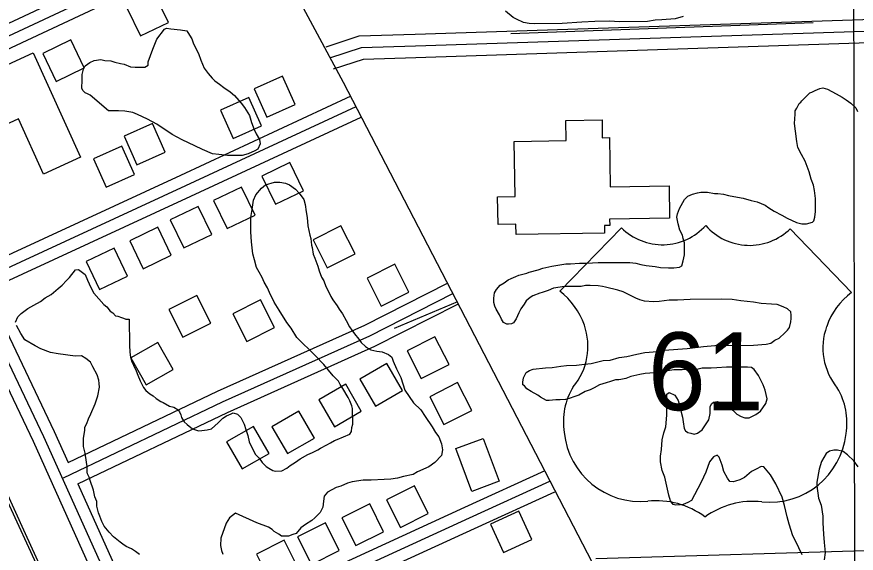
# Model space of a CAD drawing. Extents: x 3313442 to 3351311, y 721974 to 747360.
# Drawn here: x 3326984 to 3328063, y 738094 to 738784 of the extents above; entities that cross this region are included whole.
import ezdxf

# ---------------------------------------------------------------- set-up
doc = ezdxf.new("R2010")
doc.units = 0
for name, color, linetype in [('V-BLDG-OTLN', 7, 'Continuous'), ('V-GRID-MAJR', 7, 'Continuous'), ('V-RAIL-TRAK', 7, 'Continuous'), ('V-ROAD-CNTR', 7, 'Continuous'), ('V-ROAD-IDEN', 7, 'Continuous'), ('V-SITE-VEGE', 7, 'Continuous'), ('V-TOPO-SHOR', 7, 'Continuous')]:
    doc.layers.add(name, color=color, linetype=linetype)

msp = doc.modelspace()

# ---------------------------------------------------------------- linework, layer by layer
at = {"layer": 'V-BLDG-OTLN'}
for points in [[(3327162, 738812.9), (3327126, 738795.4), (3327143.5, 738759.4), (3327179.5, 738776.9)], [(3327053.7, 738754.3), (3327017.7, 738736.8), (3327035.2, 738700.8), (3327071.2, 738718.3)], [(3327005.4, 738737.5), (3327066.4, 738603.5), (3327018.9, 738581.9), (3326986.5, 738652.9), (3326962.2, 738641.8), (3326933.5, 738704.8)], [(3327305.6, 738654.9), (3327342.1, 738671.2), (3327325.8, 738707.7), (3327289.3, 738691.4)], [(3327262.6, 738627.4), (3327299.1, 738643.7), (3327282.8, 738680.2), (3327246.3, 738663.9)], [(3327602.9, 738517), (3327602.4, 738552.5), (3327624.7, 738552.8), (3327623.5, 738623.8), (3327690.3, 738624.9), (3327689.9, 738650.7), (3327736.5, 738651.5), (3327736.8, 738628.6), (3327746, 738628.7), (3327747, 738565.4), (3327822.6, 738566.6), (3327823.2, 738525.1), (3327746.3, 738523.9), (3327746.4, 738515.7), (3327739.8, 738515.6), (3327739.9, 738506), (3327626.1, 738504.2), (3327625.9, 738517.4)], [(3327138.7, 738593.9), (3327175.2, 738610.2), (3327158.9, 738646.7), (3327122.4, 738630.5)], [(3327099.3, 738565), (3327135.9, 738581.3), (3327119.6, 738617.9), (3327083, 738601.6)], [(3327335.4, 738596.5), (3327299.4, 738579.2), (3327316.7, 738543.1), (3327352.7, 738560.5)], [(3327273.4, 738565), (3327237.4, 738547.7), (3327254.7, 738511.7), (3327290.8, 738529)], [(3327217.6, 738540.2), (3327181.6, 738522.8), (3327199, 738486.8), (3327235, 738504.1)], [(3327165.6, 738513.4), (3327129.5, 738496), (3327146.9, 738460), (3327182.9, 738477.4)], [(3327419.1, 738479.5), (3327400.9, 738515.2), (3327365.3, 738497.1), (3327383.4, 738461.4)], [(3327109.4, 738486.7), (3327073.4, 738469.3), (3327090.7, 738433.3), (3327126.8, 738450.6)], [(3327488.4, 738430.2), (3327470.3, 738465.9), (3327434.6, 738447.8), (3327452.7, 738412.1)], [(3327233.7, 738390.3), (3327215.6, 738425.9), (3327179.9, 738407.8), (3327198, 738372.1)], [(3327315.6, 738384.5), (3327297.5, 738420.2), (3327261.9, 738402.1), (3327280, 738366.4)], [(3327539.9, 738337.2), (3327521.8, 738372.8), (3327486.1, 738354.7), (3327504.2, 738319.1)], [(3327150.7, 738310.7), (3327185.4, 738330.6), (3327165.5, 738365.3), (3327130.8, 738345.4)], [(3327445.2, 738283.5), (3327479.9, 738303.4), (3327460, 738338.1), (3327425.3, 738318.2)], [(3327392.5, 738257), (3327427.1, 738276.9), (3327407.2, 738311.6), (3327372.5, 738291.7)], [(3327569, 738278.1), (3327550.9, 738313.8), (3327515.2, 738295.6), (3327533.4, 738260)], [(3327332.1, 738222.4), (3327366.8, 738242.3), (3327346.9, 738277), (3327312.2, 738257.1)], [(3327273.9, 738202.9), (3327308.6, 738222.8), (3327288.7, 738257.5), (3327254, 738237.6)], [(3327569.3, 738173.8), (3327548.7, 738228.9), (3327583.8, 738242), (3327604.4, 738186.9)], [(3327477.6, 738127.4), (3327513.3, 738145.3), (3327495.5, 738181.1), (3327459.7, 738163.2)], [(3327420, 738104.2), (3327455.8, 738122.1), (3327438, 738157.9), (3327402.2, 738140)], [(3327646.3, 738112.1), (3327629.6, 738148.4), (3327593.2, 738131.8), (3327609.9, 738095.4)], [(3327363, 738079.8), (3327398.8, 738097.7), (3327381, 738133.4), (3327345.2, 738115.6)], [(3327310.3, 738057.3), (3327346.1, 738075.2), (3327328.2, 738111), (3327292.4, 738093.1)]]:
    msp.add_lwpolyline(points, close=True, dxfattribs=at)
at = {"layer": 'V-GRID-MAJR'}
msp.add_spline([(3328075.1, 727366.3), (3328067.1, 733424.9), (3328059.2, 739486.7), (3328051.3, 745548.5), (3328051.3, 745551.5)], degree=3, dxfattribs=at)
at = {"layer": 'V-RAIL-TRAK'}
msp.add_lwpolyline([(3327407.2, 737206.7), (3327346, 737342.7), (3327255.2, 737542), (3327151.4, 737770.4), (3327055.5, 737980.5), (3327019.5, 738058.9), (3326965.1, 738177.2), (3326868.8, 738389.1), (3326793.1, 738556.9), (3326699.8, 738760.5), (3326584.4, 739013.9)], dxfattribs=at)
at = {"layer": 'V-ROAD-CNTR'}
msp.add_line((3327469.7, 738383.7), (3327551, 738418), dxfattribs=at)
for points in [[(3327059, 739341.5), (3327403.8, 738699.8)], [(3326851.1, 738718.6), (3327285.4, 738921.9)], [(3326857.4, 738705), (3327291.8, 738908.3)], [(3326863.8, 738691.4), (3327298.1, 738894.8)], [(3327386.9, 738731.4), (3327427.2, 738744.4), (3327496.6, 738746.7), (3329869.9, 738824.8)], [(3327382.2, 738745.6), (3327424.6, 738759.4), (3327496.2, 738761.7), (3328176.2, 738784.1)], [(3327391.5, 738717.1), (3327429.8, 738729.5), (3327497.1, 738731.7), (3328390.2, 738761.1)], [(3327403.8, 738699.8), (3328760.8, 736081.2)], [(3327413.8, 738681.9), (3327195, 738580.2), (3326933.1, 738459.2)], [(3327420.1, 738668.3), (3327201.3, 738566.6), (3326926, 738439.3), (3326926.7, 738437.4)], [(3327426.5, 738654.7), (3327207.6, 738552.9), (3326946, 738432.1)], [(3328479, 734877.1), (3327825, 736304.4), (3326995.4, 738119.3), (3326777.2, 738600.5)], [(3326912.1, 738468.3), (3327018.9, 738244.6), (3327212.6, 737813.3), (3327328.5, 737562.7), (3327539.8, 737106.8), (3327748.9, 736642.6), (3327981.7, 736133.7), (3328101.7, 735880.4), (3328340.2, 735352.9), (3328536.1, 734929.8)], [(3326898.6, 738461.8), (3327005.3, 738238.3), (3327198.9, 737807.1), (3327314.9, 737556.4), (3327526.2, 737100.6), (3327735.2, 736636.4), (3327968.1, 736127.4), (3328035.4, 735985.4)], [(3327050.5, 738211), (3327242.4, 738302.6), (3327431.7, 738387.4), (3327537.8, 738441.5)], [(3326946, 738432.1), (3327032.5, 738250.9), (3327050.5, 738211)], [(3327044.3, 738191.5), (3327248.7, 738288.9), (3327438.2, 738373.9), (3327544.6, 738428.1)], [(3327062.8, 738183.6), (3327255, 738275.3), (3327444.7, 738360.4), (3327551.4, 738414.7)], [(3327156.9, 737974), (3327357.3, 738060.4), (3327560.2, 738153.4), (3327663.3, 738200.6)], [(3327149.2, 737954.4), (3327363.4, 738046.7), (3327566.4, 738139.8), (3327669.6, 738187)], [(3327062.8, 738183.6), (3327156.9, 737974)], [(3327169.2, 737946.7), (3327369.4, 738033), (3327572.7, 738126.2), (3327675.8, 738173.3)], [(3328103.5, 738098.3), (3327728.7, 738087)]]:
    msp.add_lwpolyline(points, dxfattribs=at)
at = {"layer": 'V-ROAD-IDEN'}
for p, q in [((3327682.2, 738431.1), (3327761.4, 738512.8)), ((3327682.2, 738431.1), (3327761.4, 738512.8)), ((3327978.5, 738511.6), (3328057.2, 738429.4)), ((3328057.2, 738429.4), (3327978.5, 738511.6)), ((3327682.2, 738431.1), (3327682.2, 738431.1))]:
    msp.add_line(p, q, dxfattribs=at)
for centre, major_axis, start_param, end_param in [((3327814.2, 738566), (-0.1, -75), 5.502702, 7.121811), ((3327814.2, 738566), (-0.1, -75), 5.502702, 7.121811), ((3327926.1, 738565.2), (0.1, 75), 2.291842, 3.917604), ((3327926.1, 738565.2), (0.1, 75), 2.291842, 3.917604), ((3327626.8, 738357.5), (0.1, 92.2), 5.045266, 5.638568), ((3327626.8, 738357.5), (0.1, 92.2), 5.045266, 5.638568), ((3328112, 738355.4), (-0.1, -92.2), 3.781672, 4.374974), ((3328112, 738355.4), (-0.1, -92.2), 3.781672, 4.374974), ((3327636.9, 738360.6), (0.1, 81.7), 4.021008, 5.049788), ((3327636.9, 738360.6), (0.1, 81.7), 4.021008, 5.049788), ((3328101.9, 738358.5), (-0.1, -81.7), 4.370452, 5.399232), ((3328101.9, 738358.5), (-0.1, -81.7), 4.370452, 5.399232), ((3327773.1, 738263.2), (-0.1, -86.5), 4.163028, 4.868958), ((3327773.1, 738263.2), (-0.1, -86.5), 4.163028, 4.868958), ((3327965, 738262.1), (0.1, 86.5), 4.551282, 5.257212), ((3327965, 738262.1), (0.1, 86.5), 4.551282, 5.257212), ((3327786, 738259.7), (0.1, 98.8), 1.672766, 3.238327), ((3327786, 738259.7), (0.1, 98.8), 1.672766, 3.238327), ((3327952.1, 738258.8), (-0.1, -98.8), 6.181885, 7.747479), ((3327952.1, 738258.8), (-0.1, -98.8), 6.181885, 7.747479), ((3327806, 738056.3), (0.1, 105.6), 5.646836, 6.385311), ((3327806, 738056.3), (0.1, 105.6), 5.646836, 6.385311), ((3327930.7, 738055.5), (-0.1, -105.6), 3.034929, 3.773404), ((3327930.7, 738055.5), (-0.1, -105.6), 3.034929, 3.773404)]:
    msp.add_ellipse(centre, major_axis=major_axis, ratio=0.99789, start_param=start_param, end_param=end_param, dxfattribs=at)
at = {"layer": 'V-SITE-VEGE'}
for points in [[(3327840.8, 738784.5), (3327830.4, 738781.3), (3327813.3, 738780), (3327804.8, 738779.9), (3327795, 738778), (3327758.9, 738777.7), (3327746.1, 738778.2), (3327727.1, 738778), (3327710.6, 738777.3), (3327685.5, 738775.3), (3327650.1, 738775), (3327642.7, 738775.5), (3327635.4, 738776.7), (3327626.8, 738780.9), (3327622.5, 738783.3), (3327612.6, 738791.2)], [(3327993.3, 738676.2), (3327999.4, 738681.8), (3328003.7, 738686.1), (3328006.1, 738687.3), (3328010.4, 738689.2), (3328016.5, 738691.7), (3328020.1, 738692.9), (3328026.2, 738691.2), (3328037.3, 738685.1), (3328045.3, 738680.9), (3328050.2, 738677.3), (3328056.4, 738673.1), (3328062.5, 738667), (3328065, 738662.1)], [(3327659.6, 738429.5), (3327656.5, 738428.9), (3327647.4, 738425.1), (3327644.3, 738423.3), (3327638.9, 738419), (3327636.5, 738414.7), (3327632.2, 738408.5), (3327629.8, 738403.6), (3327626.2, 738395.6), (3327622.6, 738390.7), (3327620.1, 738389.5), (3327616.5, 738388.8), (3327614, 738388.8), (3327609.7, 738391.2), (3327607.3, 738395.5), (3327604.8, 738401), (3327600.4, 738408.3), (3327598.6, 738411.9), (3327597.3, 738416.8), (3327597.3, 738422.3), (3327598.4, 738429), (3327600.8, 738433.3), (3327605.7, 738438.9), (3327610.6, 738442), (3327616, 738445.7), (3327619.7, 738447.6), (3327625.8, 738450), (3327629.4, 738451.9), (3327639.8, 738454.4), (3327642.9, 738455.7), (3327654.5, 738458.8), (3327660.5, 738460.7), (3327672.1, 738463.3), (3327689.9, 738466.5), (3327696, 738466.5), (3327707.6, 738467.2), (3327716.8, 738467.3), (3327731.4, 738468), (3327772.4, 738468.3), (3327779.8, 738467.2), (3327786.5, 738465.4), (3327793.2, 738464.2), (3327804.9, 738463.1), (3327811.6, 738461.9), (3327822, 738461.4), (3327828.7, 738461.5), (3327836.1, 738462.1), (3327839.1, 738464), (3327840.9, 738470.1), (3327842.7, 738478.1), (3327842.5, 738493.4), (3327840.7, 738498.9), (3327840, 738503.1), (3327836.3, 738509.8), (3327834.4, 738517.8), (3327832.5, 738526.3), (3327833.7, 738530.6), (3327836.1, 738537.4), (3327842.7, 738549), (3327846.9, 738553.3), (3327853, 738555.8), (3327859.1, 738557.7), (3327863.4, 738558.4), (3327872, 738558.4), (3327881.2, 738556.7), (3327885.4, 738556.7), (3327892.8, 738556.2), (3327898.9, 738554.4), (3327910.6, 738552), (3327917.9, 738550.9), (3327928.3, 738547.9), (3327935.7, 738546.1), (3327946.1, 738541.9), (3327951, 738538.3), (3327957.8, 738534), (3327967.6, 738529.2), (3327974.4, 738525), (3327986.6, 738519.6), (3327993.4, 738517.8), (3327999.5, 738517.9), (3328006.8, 738519.8), (3328008.6, 738521.6), (3328009.8, 738526.5), (3328011, 738533.9), (3328010.9, 738550.4), (3328009.6, 738560.8), (3328008.3, 738567.5), (3328005.2, 738575.4), (3328002.6, 738584.6), (3327997.6, 738598.6), (3327992.7, 738607.1), (3327988.3, 738616.2), (3327987, 738623.6), (3327985.1, 738637), (3327983.8, 738646.8), (3327984.9, 738659), (3327984.9, 738663.3), (3327986.7, 738666.4), (3327989.7, 738672.5), (3327992.1, 738674.4), (3327993.3, 738676.2)], [(3327121.6, 738396.7), (3327124.6, 738395.5), (3327128.9, 738395.5), (3327129.2, 738361.9), (3327129.9, 738352.7), (3327130.5, 738346.6), (3327132.4, 738340.5), (3327134.3, 738336.3), (3327138, 738329), (3327139.9, 738323.5), (3327143, 738316.2), (3327147.3, 738307.6), (3327150.4, 738303.4), (3327155.4, 738299.1), (3327159.7, 738296.7), (3327163.4, 738293.1), (3327169.5, 738289.5), (3327172.6, 738288.3), (3327180.6, 738283.4), (3327186.1, 738282.2), (3327191.6, 738278.6), (3327193.5, 738276.2), (3327195.3, 738272.5), (3327196, 738268.9), (3327199.7, 738263.4), (3327203.4, 738259.8), (3327210.2, 738254.3), (3327218.1, 738251.9), (3327222.4, 738252), (3327229.1, 738253.2), (3327234.6, 738254.5), (3327243.1, 738261.9), (3327249.2, 738268.1), (3327254, 738271.2), (3327260.1, 738273.7), (3327262.6, 738274.9), (3327268.1, 738273.1), (3327272.4, 738268.9), (3327276.8, 738260.3), (3327278.6, 738253.6), (3327281.2, 738245.7), (3327283.1, 738237.8), (3327287.4, 738228.6), (3327291.1, 738221.3), (3327296.1, 738216.5), (3327299.8, 738211), (3327304.7, 738206.1), (3327308.4, 738203.7), (3327313.3, 738200.7), (3327316.4, 738200.1), (3327324.9, 738200.2), (3327331.6, 738203.9), (3327335.9, 738207), (3327342.6, 738211.3), (3327348.7, 738215.7), (3327358.4, 738221.3), (3327364.5, 738223.7), (3327371.2, 738227.5), (3327374.9, 738229.3), (3327382.8, 738233.7), (3327387.6, 738236.2), (3327392.5, 738239.3), (3327396.2, 738240.5), (3327412.6, 738247.4), (3327414.4, 738251.1), (3327415, 738256), (3327416.2, 738260.2), (3327416, 738280.4), (3327414.8, 738284.1), (3327412.3, 738290.2), (3327410.4, 738294.4), (3327403.6, 738306), (3327399.9, 738311.5), (3327398, 738315.8), (3327391.2, 738322.4), (3327378.9, 738337), (3327367.8, 738348.5), (3327344.4, 738371.6), (3327336.9, 738383.8), (3327331.4, 738391), (3327321.5, 738406.9), (3327315.2, 738417.2), (3327309, 738429.4), (3327306.5, 738435.5), (3327302.2, 738442.8), (3327299.7, 738448.9), (3327296, 738455.6), (3327292.3, 738461.7), (3327289.7, 738471.4), (3327287.8, 738479.4), (3327285.9, 738494.6), (3327285.2, 738507.5), (3327285, 738525.8), (3327286.8, 738536.2), (3327288.5, 738548.5), (3327291.5, 738555.2), (3327298.8, 738563.9), (3327304.2, 738568.2), (3327315.8, 738571.3), (3327322.6, 738571.4), (3327329.9, 738570.2)], [(3327329.9, 738570.2), (3327334.8, 738567.8), (3327342.8, 738562.4), (3327347.1, 738557.5), (3327353.3, 738549), (3327355.2, 738542.9), (3327356.5, 738533.1), (3327357.8, 738525.8), (3327358.5, 738515.4), (3327361, 738503.2), (3327362.3, 738498.9), (3327363, 738490.4), (3327364.2, 738487.3), (3327365.5, 738478.8), (3327367.4, 738473.9), (3327371.1, 738463.5), (3327373, 738457.4), (3327376.1, 738449.5), (3327379.2, 738444.6), (3327381.7, 738437.3), (3327384.2, 738432.4), (3327388, 738424.5), (3327390.4, 738420.3), (3327396, 738412.4), (3327398.5, 738408.1), (3327402.8, 738402), (3327407.8, 738393.5), (3327412.1, 738385.6), (3327415.2, 738381.3), (3327418.3, 738376.5), (3327423.9, 738369.8), (3327427, 738365.5), (3327432.5, 738360.1), (3327436.2, 738357.6), (3327439.3, 738355.8), (3327447.2, 738354.1), (3327454, 738353.5), (3327462, 738349.9), (3327466.3, 738346.3), (3327468.1, 738341.4), (3327472.5, 738331.6), (3327478.1, 738320.1), (3327483.1, 738304.2), (3327494.3, 738287.8), (3327503.5, 738278.7), (3327509.1, 738270.2), (3327518.4, 738256.8), (3327522.7, 738249.5), (3327527, 738244), (3327530.1, 738234.9), (3327531.4, 738227.5), (3327530.3, 738220.2), (3327521.8, 738210.9), (3327513.9, 738205.4), (3327499.2, 738199.1), (3327493.8, 738195.4), (3327481.6, 738192.9), (3327473.6, 738191), (3327465.1, 738189.7), (3327456.5, 738189), (3327440, 738188.3), (3327429.6, 738188.2), (3327415.6, 738186.2), (3327409.5, 738184.4), (3327400.9, 738180.6), (3327394.8, 738178.7), (3327383.9, 738173.1), (3327379.6, 738167.6), (3327378.5, 738161.5), (3327377.9, 738153.5), (3327374.3, 738146.8), (3327367.6, 738140), (3327363.4, 738136.3), (3327355.5, 738131.3), (3327349.4, 738127), (3327343.3, 738119.6), (3327339.1, 738118.4), (3327333.6, 738116.5), (3327324.4, 738116.4), (3327321.3, 738118.8), (3327315.2, 738122.4), (3327312.7, 738124.9), (3327307.8, 738127.9), (3327293.1, 738133.3), (3327265.4, 738145.9), (3327257.6, 738139.7), (3327253.3, 738133), (3327246.7, 738113.9), (3327246.2, 738104.2), (3327247.5, 738098.1), (3327249.4, 738093.2)], [(3326982.8, 738391.3), (3326985.8, 738398.1), (3326990, 738402.4), (3326998.5, 738409.2), (3327006.4, 738413.5), (3327015, 738417.9), (3327021, 738422.8), (3327028.4, 738427.1), (3327037.5, 738434.6), (3327042.9, 738438.9), (3327048.4, 738445), (3327052, 738448.7), (3327059.9, 738458.6), (3327063.6, 738459.2), (3327072.2, 738452.6), (3327075.3, 738445.3), (3327079.6, 738436.1), (3327083.4, 738428.8), (3327096.3, 738414.2), (3327100, 738411.2), (3327104.4, 738405.7), (3327108, 738403.3), (3327111.1, 738399.7), (3327114.2, 738399.1), (3327119.1, 738397.3), (3327121.6, 738396.7)], [(3327876.9, 738332.2), (3327865.2, 738332.1), (3327858.5, 738330.8), (3327846.3, 738330.7), (3327839.6, 738330.1), (3327828.6, 738330), (3327804.1, 738326.1), (3327791.9, 738325.4), (3327785.2, 738324.1), (3327773.6, 738321.6), (3327766.9, 738319.1), (3327760.8, 738317.8), (3327758.3, 738317.2), (3327754, 738317.1), (3327747.3, 738315.3), (3327741.8, 738313.4), (3327733.3, 738310.9), (3327726.6, 738307.1), (3327721.1, 738304.6), (3327715, 738302.2), (3327706.5, 738297.8), (3327701.6, 738295.9), (3327694.3, 738293.4), (3327689.4, 738292.2), (3327682.7, 738291.5), (3327677.2, 738291.5), (3327668.6, 738290.8), (3327665, 738290.7), (3327657.6, 738295), (3327653.9, 738297.4), (3327645.3, 738302.2), (3327639.8, 738305.8), (3327636.7, 738309.5), (3327634.8, 738310.7), (3327634.8, 738314.4), (3327635.4, 738319.9), (3327639, 738326.6), (3327643.3, 738329.1), (3327648.1, 738331), (3327664, 738332.9), (3327672.6, 738333), (3327683.6, 738334.9), (3327690.9, 738335.6), (3327703.7, 738336.3), (3327714.1, 738337.6), (3327722.7, 738338.3), (3327729.4, 738340.2), (3327737.9, 738342.1), (3327747.1, 738342.8), (3327758.7, 738345.9), (3327768.5, 738347.2), (3327781.3, 738350.4), (3327791.7, 738352.3), (3327807.6, 738353.7), (3327816.7, 738355.6), (3327833.8, 738356.9), (3327846.1, 738357.6), (3327866.8, 738360.2), (3327881.5, 738361.6), (3327931, 738362), (3327947.5, 738363.3), (3327953.6, 738364.6), (3327958.5, 738368.3), (3327964, 738370.8), (3327971.3, 738377.6), (3327974.9, 738381.3), (3327977.3, 738384.4), (3327979.1, 738391.7), (3327979.7, 738396), (3327979.7, 738400.3), (3327979, 738404.6), (3327974.7, 738408.8), (3327969.2, 738411.2), (3327961.8, 738414.2), (3327954.5, 738414.8), (3327941, 738415.3), (3327931.2, 738417), (3327914.7, 738418.7), (3327903.7, 738420.5), (3327889.6, 738421), (3327849.8, 738420.7), (3327833.3, 738419.9), (3327822.9, 738419.8), (3327810.1, 738417.9), (3327802.8, 738417.8), (3327791.1, 738418.3), (3327785, 738420.1), (3327780.1, 738422.5), (3327772.1, 738426.1), (3327763.5, 738430.4), (3327756.8, 738432.8), (3327740.9, 738436.3), (3327737.2, 738437.5), (3327731.7, 738438.1), (3327721.3, 738438.6), (3327715.2, 738438.5), (3327709.7, 738437.3), (3327688.3, 738437.1), (3327674.2, 738435.1), (3327667.5, 738432), (3327659.6, 738429.5)], [(3327142.3, 738092.9), (3327136.8, 738096.6), (3327131.9, 738100.2), (3327125.1, 738103.2), (3327120.8, 738106.2), (3327117.1, 738108.6), (3327115.3, 738110.4), (3327108.5, 738115.3), (3327103, 738121.3), (3327096.8, 738129.3), (3327093.7, 738135.3), (3327091.2, 738142), (3327089.3, 738146.3), (3327087.4, 738154.9), (3327087.4, 738161), (3327084.9, 738167.1), (3327083, 738175.6), (3327078.6, 738187.8), (3327077.3, 738192.1), (3327075.5, 738196.3), (3327074.8, 738198.8), (3327074.8, 738206.1), (3327074.1, 738211.6), (3327072.2, 738223.2), (3327070.3, 738231.8), (3327070.2, 738242.2), (3327070.8, 738247.1), (3327072, 738252.6), (3327071.9, 738256.3), (3327074.3, 738261.2), (3327076.7, 738267.3), (3327079.7, 738273.4), (3327085.1, 738286.3), (3327088.7, 738296.8), (3327090.5, 738307.8), (3327090.4, 738312.7), (3327089.8, 738316.9), (3327087.9, 738323.7), (3327082.3, 738334), (3327079.2, 738340.1), (3327073, 738344.9), (3327067.5, 738348), (3327059.6, 738347.9), (3327037.5, 738350.8), (3327027.7, 738352.5), (3327015.5, 738357.3), (3327008.1, 738360.9), (3326994.6, 738368.8), (3326989.6, 738376.7), (3326984, 738387)], [(3327993.8, 738092.2), (3327985, 738110.5), (3327981.9, 738116.6), (3327976.9, 738131.8), (3327974.4, 738141), (3327971.2, 738155.6), (3327968.1, 738166.6), (3327960, 738183.6), (3327953.2, 738195.2), (3327944.5, 738205.5), (3327940.9, 738206.1), (3327934.8, 738202.4), (3327928.7, 738199.3), (3327919.6, 738191.9), (3327913.5, 738188.8), (3327908, 738186.9), (3327904.9, 738186.3), (3327900.6, 738186.8), (3327897.6, 738191.1), (3327893.2, 738199.6), (3327890.7, 738207.6), (3327886.9, 738217.9), (3327884.5, 738220.3), (3327879.6, 738218.5), (3327874.8, 738211.7), (3327870, 738198.8), (3327864, 738185.9), (3327855.5, 738169.4), (3327851.3, 738162), (3327847, 738159.5), (3327841, 738157), (3327837.3, 738156.4), (3327831.2, 738156.3), (3327828.1, 738156.9), (3327824.4, 738161.8), (3327822.5, 738169.1), (3327817.4, 738192.3), (3327813.7, 738200.8), (3327811.8, 738211.8), (3327811.7, 738219.1), (3327812.9, 738227.7), (3327814, 738240), (3327815.8, 738249.1), (3327818.7, 738257.1), (3327819.9, 738271.8), (3327819.6, 738298.7), (3327822.7, 738301.2), (3327830, 738297.6), (3327834.4, 738290.9), (3327840, 738269.5), (3327840.7, 738263.4), (3327842, 738254.9), (3327843.9, 738251.8), (3327846.9, 738249.4), (3327850.6, 738248.8), (3327854.9, 738247.6), (3327859.2, 738248.9), (3327865.3, 738253.2), (3327873.7, 738266.1), (3327875.5, 738274.1), (3327875.4, 738282.7), (3327877.2, 738286.3), (3327879.6, 738288.8), (3327884.5, 738289.5), (3327894.3, 738286.5), (3327900.5, 738282.2), (3327909.7, 738273.1), (3327915.3, 738270.1), (3327920.2, 738268.3), (3327925.7, 738268.4), (3327934.2, 738272.7), (3327940.3, 738277.1), (3327946.9, 738286.9), (3327948.7, 738293), (3327946.2, 738304), (3327943.7, 738310.7), (3327937.5, 738322.9), (3327931.9, 738330.8), (3327928.8, 738333.2), (3327923.3, 738333.8), (3327896.4, 738333.6), (3327884.2, 738332.9), (3327876.9, 738332.2)], [(3328034.3, 738227.1), (3328028.8, 738225.8), (3328024.5, 738222.7), (3328018.5, 738212.2), (3328015.5, 738202.4), (3328012.6, 738185.9), (3328012.6, 738181), (3328014.6, 738165.1), (3328018.3, 738156), (3328020.3, 738141.9), (3328020.3, 738133.4), (3328021.1, 738118.7), (3328021.8, 738108.3), (3328023.1, 738095.5), (3328021.9, 738085.7)], [(3328065.6, 738205.3), (3328060, 738213.2), (3328052, 738221.1), (3328046.5, 738225.3), (3328039.1, 738227.1), (3328034.3, 738227.1)]]:
    msp.add_lwpolyline(points, dxfattribs=at)
msp.add_lwpolyline([(3327102.3, 738663.2), (3327078.9, 738683.2), (3327075.2, 738685), (3327072.1, 738686.2), (3327069.1, 738689.2), (3327067.8, 738692.3), (3327068.3, 738702.7), (3327068.3, 738710), (3327070.1, 738716.7), (3327072.5, 738721), (3327078.5, 738725.4), (3327084, 738727.9), (3327092.6, 738729.2), (3327097.5, 738728), (3327105.4, 738727.4), (3327110.3, 738725.6), (3327117.7, 738723.8), (3327122.6, 738723.3), (3327130.6, 738719.7), (3327136.7, 738719.1), (3327148.9, 738719.2), (3327153.2, 738721.7), (3327153.2, 738726), (3327159.1, 738742.5), (3327164.5, 738755.4), (3327174.2, 738768.3), (3327176.7, 738769.6), (3327182.2, 738768.4), (3327195, 738767.3), (3327203, 738766.1), (3327204.2, 738763.7), (3327209.2, 738755.8), (3327211.7, 738749.1), (3327217.9, 738736.9), (3327221, 738728.3), (3327225.4, 738718), (3327230.3, 738711.3), (3327235.3, 738705.2), (3327239, 738701.6), (3327245.1, 738697.4), (3327250.7, 738693.1), (3327258.6, 738687.7), (3327264.2, 738682.8), (3327272.8, 738673.1), (3327277.2, 738667.6), (3327283.4, 738657.3), (3327285.9, 738648.1), (3327289.6, 738639), (3327292.1, 738633.5), (3327296.4, 738626.2), (3327297.1, 738620.7), (3327294.1, 738614), (3327290.5, 738611.5), (3327281.9, 738607.8), (3327274, 738605.9), (3327255, 738605.7), (3327244, 738606.8), (3327236.1, 738608), (3327223.2, 738613.4), (3327213.3, 738618.2), (3327196.8, 738626), (3327183.9, 738632.6), (3327164.2, 738645.9), (3327152.5, 738652.6), (3327139.6, 738658.6), (3327133.5, 738661), (3327123.1, 738662.7), (3327115.1, 738663.3)], close=True, dxfattribs=at)
at = {"layer": 'V-TOPO-SHOR'}
msp.add_line((3327619.4, 738762.7), (3328008, 738776.5), dxfattribs=at)

# ---------------------------------------------------------------- texts
at = {"layer": 'V-ROAD-IDEN'}
msp.add_text('61', height=100, rotation=359.9256, dxfattribs=at).set_placement((3327795.4, 738278.4))

doc.saveas('drawing.dxf')
